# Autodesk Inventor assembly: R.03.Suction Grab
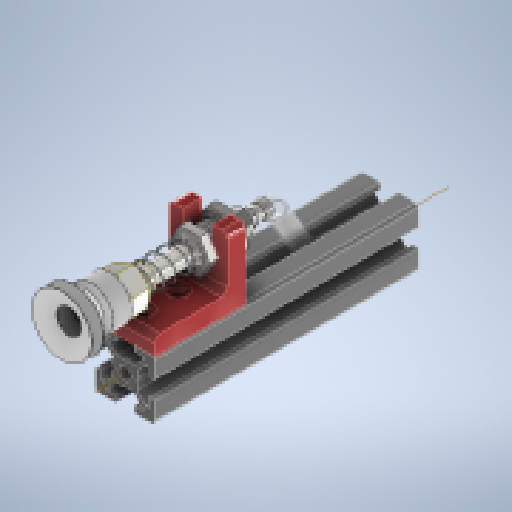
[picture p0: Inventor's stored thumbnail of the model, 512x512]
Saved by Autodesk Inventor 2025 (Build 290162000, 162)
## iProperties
Created: 2021-02
Part Number: R.03.Suction Grab
Document SubType Name: Assembly
Designer: Михальчик
Author: Михальчик
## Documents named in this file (11)
- C:\Users\Ryzen5700u\Desktop\robot_cicloidale_singolo\Workgroups\NotInProject\ventosa_20mm.iam
- C:\Users\Ryzen5700u\Desktop\robot_cicloidale_singolo\Workgroups\NotInProject\R.03.01.Cup.ipt
- C:\Users\Ryzen5700u\Desktop\robot_cicloidale_singolo\Workgroups\NotInProject\R.03.02.Tube.ipt
- C:\Users\Ryzen5700u\Desktop\robot_cicloidale_singolo\Workgroups\NotInProject\Compress Spring11.ipt
- C:\Users\Ryzen5700u\Desktop\robot_cicloidale_singolo\Workgroups\NotInProject\R.03.04.Fitting.ipt
- C:\Users\Ryzen5700u\Desktop\robot_cicloidale_singolo\Workgroups\NotInProject\DIN 3771 - 5 x 1,8 - N - NBR 70(2).ipt
- C:\Users\Ryzen5700u\Desktop\robot_cicloidale_singolo\Workgroups\NotInProject\R.03.05.Interface.ipt
- C:\Users\Ryzen5700u\Desktop\robot_cicloidale_singolo\Workgroups\NotInProject\R.03.06.Nut.ipt
- C:\Users\Ryzen5700u\Desktop\robot_cicloidale_singolo\Workgroups\NotInProject\blocco_ventosa_profilato.ipt
- C:\Users\Ryzen5700u\Desktop\robot_cicloidale_singolo\Workgroups\NotInProject\tubo_silicone.ipt
- C:\Users\Ryzen5700u\Desktop\robot_cicloidale_singolo\Workgroups\NotInProject\tslot-20x20-ventosa.ipt
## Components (10 placed, 10 different names)
1. R.03.01.Cup:1 — Mate:1, Mate:2
2. R.03.02.Tube:1 — Mate:1, Mate:2, Mate:3, Flush:1, Mate:4, Mate:6, Rigido:1, Coincidente:12
3. R.03.03.Spring:1 — Mate:3, Flush:1, Mate:7
4. R.03.04.Fitting:1 — Mate:4, Rigido:1, Allineato:4
5. DIN 3771 - 5 x 1,8 - N - NBR 70(2):1 — Rotazionale:1
6. R.03.05.Interface:1 — Mate:6, Mate:7, Mate:8, Rotazionale:1, Angolo:2, Coincidente:11
7. R.03.06.Nut:1 — Mate:8, Coincidente:13
8. blocco_ventosa_profilato:1
9. tslot-20x20-ventosa:1 — Coincidente:10, Allineato:2, Allineato:5
10. tubo_silicone:1 — Allineato:4
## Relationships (18: Mate 11, Flush 4, RevoluteJoint 1, WeldJoint 1, Angle 1)
- Mate:1: R.03.01.Cup:1 ↔ R.03.02.Tube:1
- Mate:2: R.03.01.Cup:1 ↔ R.03.02.Tube:1
- Mate:3: R.03.02.Tube:1 ↔ R.03.03.Spring:1
- Flush:1: R.03.02.Tube:1 ↔ R.03.03.Spring:1
- Mate:4: R.03.02.Tube:1 ↔ R.03.04.Fitting:1
- Mate:6: R.03.02.Tube:1 ↔ R.03.05.Interface:1
- Mate:7: R.03.03.Spring:1 ↔ R.03.05.Interface:1
- Mate:8: R.03.05.Interface:1 ↔ R.03.06.Nut:1
- Rotazionale:1 [RevoluteJoint]: DIN 3771 - 5 x 1,8 - N - NBR 70(2):1 ↔ R.03.05.Interface:1
- Rigido:1 [WeldJoint]: R.03.02.Tube:1 ↔ R.03.04.Fitting:1
- Coincidente:10 [Mate]: tslot-20x20-ventosa:1
- Allineato:2 [Flush]: tslot-20x20-ventosa:1
- Allineato:4 [Flush]: R.03.04.Fitting:1 ↔ tubo_silicone:1
- Angolo:2 [Angle]: R.03.05.Interface:1
- Coincidente:11 [Mate]: R.03.05.Interface:1
- Allineato:5 [Flush]: tslot-20x20-ventosa:1
- Coincidente:12 [Mate]: R.03.02.Tube:1
- Coincidente:13 [Mate]: R.03.06.Nut:1
